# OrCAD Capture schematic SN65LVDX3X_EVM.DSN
size B; rev: C
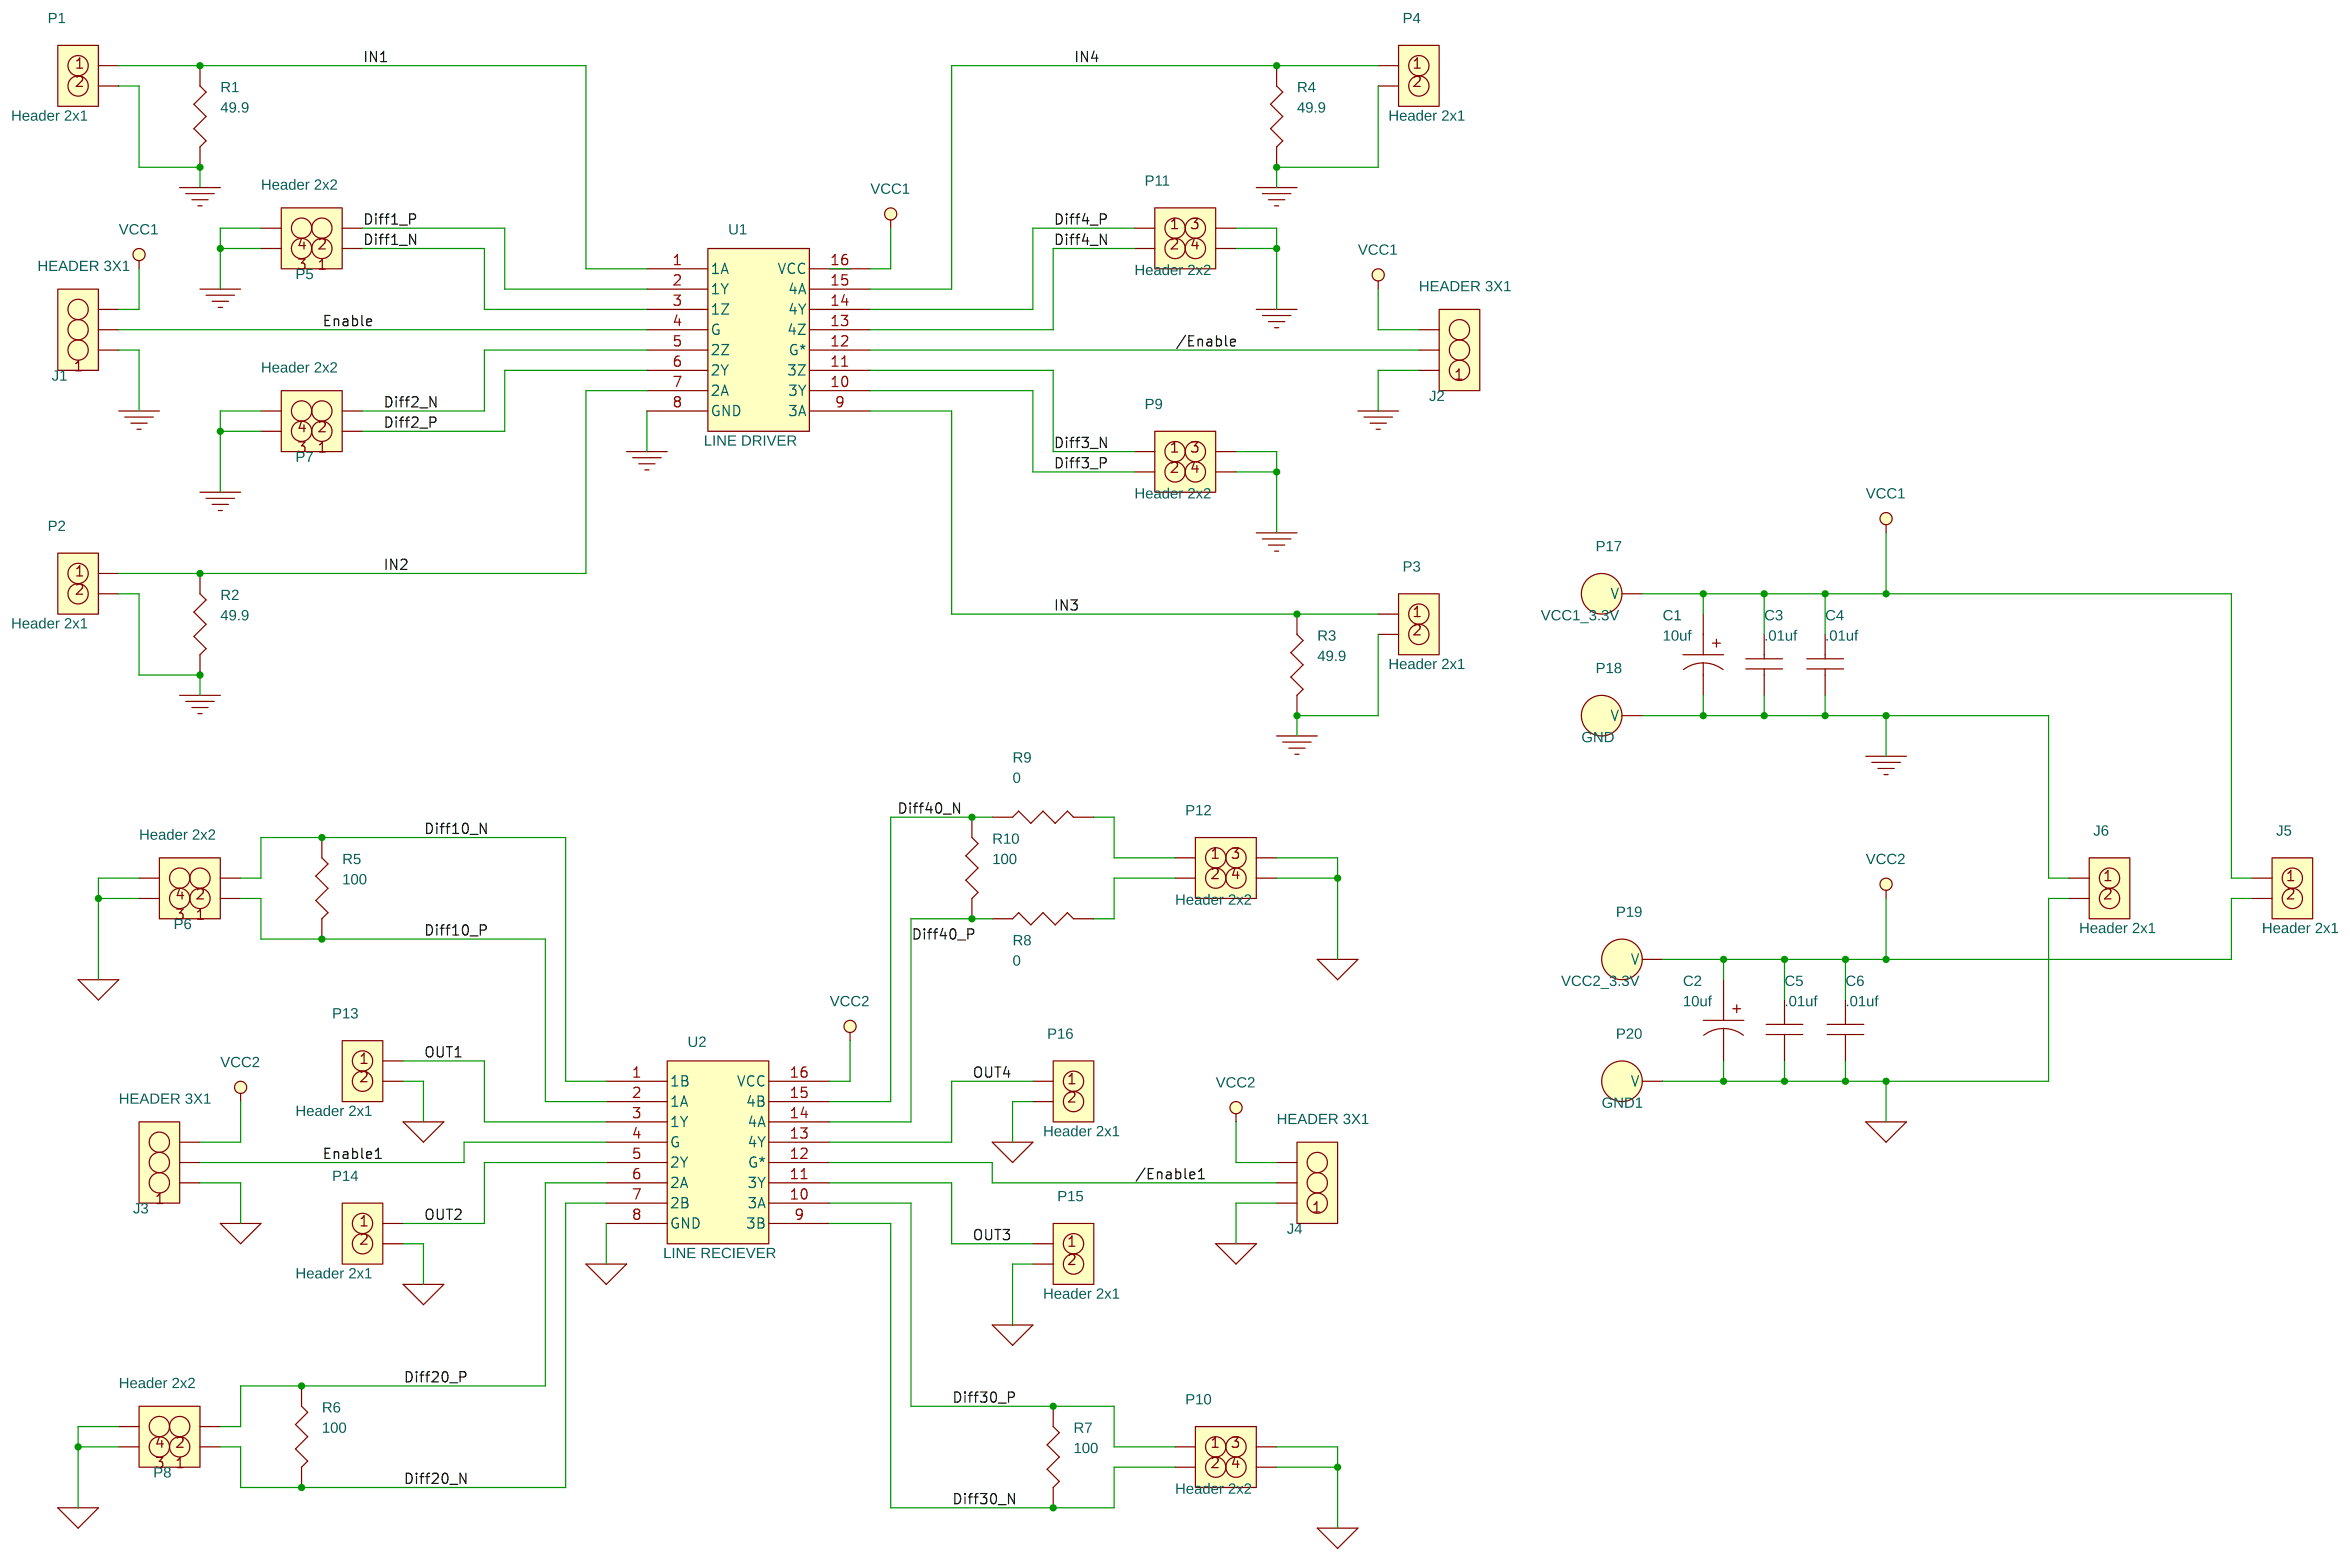
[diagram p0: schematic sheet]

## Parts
C1  10uf  [cc7343]
C2  10uf  [cc7343]
C3  .01uf  [cc0805]
C4  .01uf  [cc0805]
C5  .01uf  [cc0805]
C6  .01uf  [cc0805]
J1  HEADER 3X1  [berg1x3]
J2  HEADER 3X1  [berg1x3]
J3  HEADER 3X1  [berg1x3]
J4  HEADER 3X1  [berg1x3]
J5  Header 2x1  [berg2]
J6  Header 2x1  [berg2]
P1  Header 2x1  [berg2]
P2  Header 2x1  [berg2]
P3  Header 2x1  [berg2]
P4  Header 2x1  [berg2]
P5  Header 2x2  [BERG2X2]
P6  Header 2x2  [BERG2X2]
P7  Header 2x2  [BERG2X2]
P8  Header 2x2  [BERG2X2]
P9  Header 2x2  [BERG2X2]
P10  Header 2x2  [BERG2X2]
P11  Header 2x2  [BERG2X2]
P12  Header 2x2  [BERG2X2]
P13  Header 2x1  [berg2]
P14  Header 2x1  [berg2]
P15  Header 2x1  [berg2]
P16  Header 2x1  [berg2]
P17  VCC1_3.3V  [bjack]
P18  GND  [bjack]
P19  VCC2_3.3V  [bjack]
P20  GND1  [bjack]
R1  49.9  [r0603]
R2  49.9  [r0603]
R3  49.9  [r0603]
R4  49.9  [r0603]
R5  100  [r0603]
R6  100  [r0603]
R7  100  [r0603]
R8  0  [r0603]
R9  0  [r0603]
R10  100  [r0603]
U1  LINE DRIVER  [D16]
U2  LINE RECIEVER  [D16]

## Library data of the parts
C1 C2 = PCap7343_10uf: CAP TANT 10UF 35V 10% 2917; Manufacturer: Vishay Sprague; Part_Number: 293D106X9035D2TE3
C3-C6 = NPCap0805_0.01uf: CAP CER 10000PF 100V X7R 0805; Manufacturer: AVX Corporation; Part_Number: 08051C103JAT2A
J1-J4 = Header_3x1: CONN HEADER 3POS .100" T/H GOLD; MANUFACTURER: Samtec Inc.; Part_Number: HTSW-103-07-G-S
J5 J6 P1-P4 P13-P16 = Header_2x1: CONN HEADER 2POS .100" T/H GOLD; MANUFACTURER: Samtec Inc.; Part_Number: HTSW-102-07-G-S
P5-P12 = Header_2x2_0: CONN HEADER 4POS .100" DUAL GOLD; MANUFACTURER: Samtec Inc.; Part_Number: TSW-102-07-G-D
P17-P20 = Banana-Jack
R1-R4 = r0603: RES SMD 49.9 OHM 1% 1/10W 0603; MANUFACTURER: Stackpole Electronics Inc.; Part_Number: RMCF0603FT49R9
R5-R7 R10 = r0603: RES SMD 100 OHM 1% 1/10W 0603; MANUFACTURER: Stackpole Electronics Inc.; Part_Number: RMCF0603FT100R
R8 R9 = r0603: RES SMD 0.0OHM JUMPER 1/10W 0603; MANUFACTURER: Stackpole Electronics Inc.; Part_Number: RMCF0603ZT0R00
U1 = 16_PIN_DEVICE_1
U2 = 16_PIN_DEVICE_2

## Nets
GND_POWER: C1.2 C3.2 C4.2 J1.1 J2.1 J6.1 P1.2 P2.2 P3.2 P4.2 P5.2 P5.4 P7.2 P7.4 P9.2 P9.4 P11.2 P11.4 P18.1(V) R1.2 R2.2 R3.2 R4.2 U1.8(GND)
GND_SIGNAL: C2.2 C5.2 C6.2 J3.1 J4.1 J6.2 P6.2 P6.4 P8.2 P8.4 P10.2 P10.4 P12.2 P12.4 P13.2 P14.2 P15.2 P16.2 P20.1(V) U2.8(GND)
VCC1: C1.1 C3.1 C4.1 J1.3 J2.3 J5.1 P17.1(V) U1.16(VCC)
VCC2: C2.1 C5.1 C6.1 J3.3 J4.3 J5.2 P19.1(V) U2.16(VCC)
/Enable: J2.2 U1.12(G*)
/Enable1: J4.2 U2.12(G*)
Diff1_N: P5.1 U1.3(1Z)
Diff1_P: P5.3 U1.2(1Y)
Diff2_N: P7.3 U1.5(2Z)
Diff2_P: P7.1 U1.6(2Y)
Diff3_N: P9.1 U1.11(3Z)
Diff3_P: P9.3 U1.10(3Y)
Diff4_N: P11.3 U1.13(4Z)
Diff4_P: P11.1 U1.14(4Y)
Diff10_N: P6.3 R5.1 U2.1(1B)
Diff10_P: P6.1 R5.2 U2.2(1A)
Diff20_N: P8.1 R6.2 U2.7(2B)
Diff20_P: P8.3 R6.1 U2.6(2A)
Diff30_N: P10.3 R7.2 U2.9(3B)
Diff30_P: P10.1 R7.1 U2.10(3A)
Diff40_N: R9.1 R10.1 U2.15(4B)
Diff40_P: R8.2 R10.2 U2.14(4A)
Enable: J1.2 U1.4(G)
Enable1: J3.2 U2.4(G)
IN1: P1.1 R1.1 U1.1(1A)
IN2: P2.1 R2.1 U1.7(2A)
IN3: P3.1 R3.1 U1.9(3A)
IN4: P4.1 R4.1 U1.15(4A)
OUT1: P13.1 U2.3(1Y)
OUT2: P14.1 U2.5(2Y)
OUT3: P15.1 U2.11(3Y)
OUT4: P16.1 U2.13(4Y)
N179608: P12.3 R8.1
N180034: P12.1 R9.2
